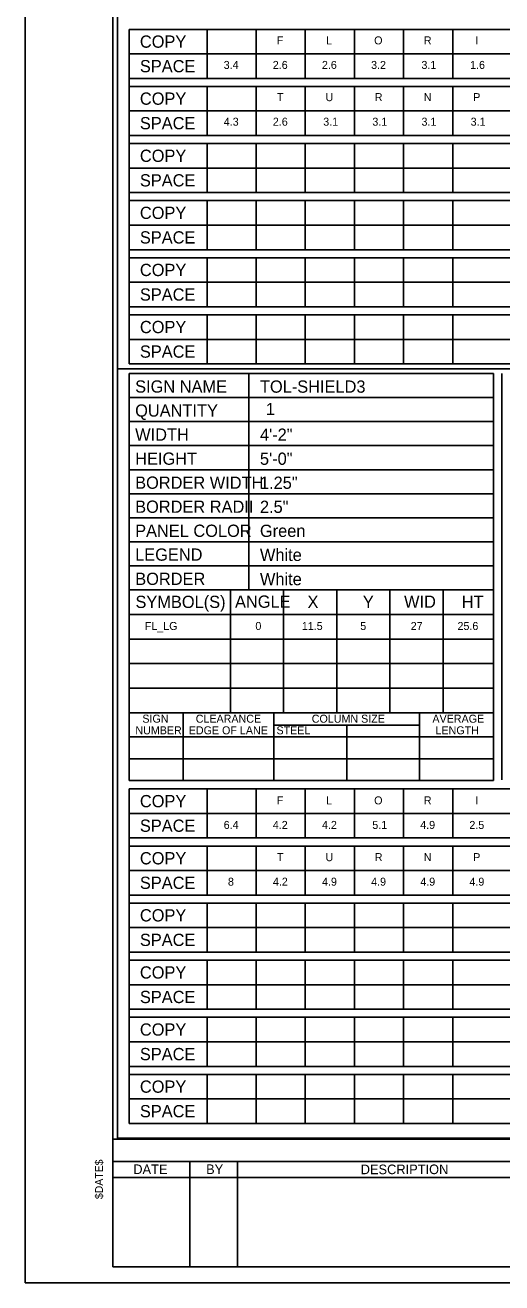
# Model space of a CAD drawing. Extents: x 17890628 to 17890844, y 17897693 to 17898031.
# Drawn here: x 17890700.5 to 17890726.4, y 17897907.6 to 17897976.1 of the extents above; entities that cross this region are included whole.
import ezdxf

# ---------------------------------------------------------------- set-up
doc = ezdxf.new("R2010")
doc.units = 0
for name, color, linetype in [('GSSign', 7, 'Continuous'), ('PlotBorder_dp', 7, 'Continuous'), ('SheetBorder_dp', 7, 'Continuous'), ('SheetLines_dp', 7, 'Continuous'), ('SheetLinesMisc2_dp', 7, 'Continuous'), ('TextMinor', 7, 'Continuous'), ('TextMisc', 7, 'Continuous')]:
    doc.layers.add(name, color=color, linetype=linetype)

msp = doc.modelspace()

# ---------------------------------------------------------------- linework, layer by layer
at = {"layer": 'PlotBorder_dp'}
msp.add_lwpolyline([(17890700.471, 17897907.61), (17890843.989, 17897907.61), (17890843.989, 17897999.809), (17890700.471, 17897999.809)], close=True, dxfattribs=at)
at = {"layer": 'SheetBorder_dp'}
for p, q in [((17890705.254, 17897998.94), (17890705.254, 17897908.479)), ((17890705.254, 17897915.438), (17890839.205, 17897915.438)), ((17890705.254, 17897908.479), (17890839.205, 17897908.479))]:
    msp.add_line(p, q, dxfattribs=at)
at = {"layer": 'SheetLines_dp'}
for p, q in [((17890705.254, 17897914.22), (17890755.355, 17897914.22)), ((17890709.43, 17897914.22), (17890709.43, 17897908.479)), ((17890712.039, 17897914.22), (17890712.039, 17897908.479)), ((17890705.254, 17897913.35), (17890755.355, 17897913.35))]:
    msp.add_line(p, q, dxfattribs=at)
at = {"layer": 'SheetLinesMisc2_dp'}
for p, q in [((17890705.5, 17897998.732), (17890705.5, 17897915.484)), ((17890706.142, 17897975.843), (17890771.912, 17897975.843)), ((17890706.142, 17897957.633), (17890706.142, 17897975.843)), ((17890710.375, 17897975.843), (17890710.375, 17897973.171)), ((17890713.051, 17897975.843), (17890713.051, 17897973.171)), ((17890715.727, 17897975.843), (17890715.727, 17897973.171)), ((17890718.402, 17897975.843), (17890718.402, 17897973.171)), ((17890721.077, 17897975.843), (17890721.077, 17897973.171)), ((17890723.753, 17897975.843), (17890723.753, 17897973.171)), ((17890706.142, 17897974.507), (17890771.912, 17897974.507)), ((17890706.142, 17897973.171), (17890771.912, 17897973.171)), ((17890706.142, 17897972.735), (17890771.912, 17897972.735)), ((17890710.375, 17897972.735), (17890710.375, 17897970.064)), ((17890713.051, 17897972.735), (17890713.051, 17897970.064)), ((17890715.727, 17897972.735), (17890715.727, 17897970.064)), ((17890718.402, 17897972.735), (17890718.402, 17897970.064)), ((17890721.077, 17897972.735), (17890721.077, 17897970.064)), ((17890723.753, 17897972.735), (17890723.753, 17897970.064)), ((17890706.142, 17897971.399), (17890771.912, 17897971.4)), ((17890706.142, 17897970.064), (17890771.912, 17897970.064)), ((17890706.142, 17897969.628), (17890771.912, 17897969.628)), ((17890710.375, 17897969.628), (17890710.375, 17897966.956)), ((17890713.051, 17897969.628), (17890713.051, 17897966.956)), ((17890715.727, 17897969.628), (17890715.727, 17897966.956)), ((17890718.402, 17897969.628), (17890718.402, 17897966.956)), ((17890721.077, 17897969.628), (17890721.077, 17897966.956)), ((17890723.753, 17897969.628), (17890723.753, 17897966.956)), ((17890706.142, 17897968.292), (17890771.912, 17897968.292)), ((17890706.142, 17897966.956), (17890771.912, 17897966.956)), ((17890706.142, 17897966.52), (17890771.912, 17897966.52)), ((17890710.375, 17897966.52), (17890710.375, 17897963.848)), ((17890713.051, 17897966.52), (17890713.051, 17897963.848)), ((17890715.727, 17897966.52), (17890715.727, 17897963.848)), ((17890718.402, 17897966.52), (17890718.402, 17897963.848)), ((17890721.077, 17897966.52), (17890721.077, 17897963.848)), ((17890723.753, 17897966.52), (17890723.753, 17897963.848)), ((17890706.142, 17897965.184), (17890771.912, 17897965.184)), ((17890706.142, 17897963.848), (17890771.912, 17897963.848)), ((17890706.142, 17897963.412), (17890771.912, 17897963.412)), ((17890710.375, 17897963.412), (17890710.375, 17897960.74)), ((17890713.051, 17897963.412), (17890713.051, 17897960.74)), ((17890715.727, 17897963.412), (17890715.727, 17897960.74)), ((17890718.402, 17897963.412), (17890718.402, 17897960.74)), ((17890721.077, 17897963.412), (17890721.077, 17897960.74)), ((17890723.753, 17897963.412), (17890723.753, 17897960.74)), ((17890706.142, 17897962.076), (17890771.912, 17897962.076)), ((17890706.142, 17897960.74), (17890771.912, 17897960.74)), ((17890706.142, 17897960.304), (17890771.912, 17897960.304)), ((17890710.375, 17897960.304), (17890710.375, 17897957.633)), ((17890713.051, 17897960.304), (17890713.051, 17897957.633)), ((17890715.727, 17897960.304), (17890715.727, 17897957.633)), ((17890718.402, 17897960.304), (17890718.402, 17897957.633)), ((17890721.077, 17897960.304), (17890721.077, 17897957.633)), ((17890723.753, 17897960.304), (17890723.753, 17897957.633)), ((17890706.142, 17897958.969), (17890771.912, 17897958.969)), ((17890705.5, 17897957.37), (17890839.233, 17897957.37)), ((17890706.142, 17897957.633), (17890771.912, 17897957.633)), ((17890706.142, 17897934.953), (17890706.142, 17897957.108)), ((17890706.142, 17897957.108), (17890725.973, 17897957.108)), ((17890712.643, 17897957.108), (17890712.643, 17897955.799)), ((17890725.973, 17897957.108), (17890725.973, 17897934.953)), ((17890726.429, 17897957.109), (17890726.429, 17897934.985)), ((17890706.142, 17897955.799), (17890725.973, 17897955.799)), ((17890712.643, 17897955.799), (17890712.643, 17897945.327)), ((17890706.142, 17897954.491), (17890725.973, 17897954.491)), ((17890706.142, 17897953.182), (17890725.973, 17897953.182)), ((17890706.142, 17897951.874), (17890725.973, 17897951.874)), ((17890706.142, 17897950.565), (17890725.973, 17897950.565)), ((17890706.142, 17897949.256), (17890725.973, 17897949.256)), ((17890706.142, 17897947.948), (17890716.057, 17897947.948)), ((17890716.057, 17897947.948), (17890725.973, 17897947.948)), ((17890706.142, 17897946.639), (17890716.057, 17897946.639)), ((17890716.057, 17897946.639), (17890725.973, 17897946.639)), ((17890706.141, 17897945.327), (17890725.973, 17897945.327)), ((17890711.644, 17897945.327), (17890711.644, 17897938.646)), ((17890714.542, 17897945.327), (17890714.542, 17897938.646)), ((17890717.44, 17897945.327), (17890717.44, 17897938.646)), ((17890720.337, 17897945.327), (17890720.337, 17897938.646)), ((17890723.235, 17897945.327), (17890723.235, 17897938.646)), ((17890706.141, 17897943.991), (17890725.973, 17897943.991)), ((17890706.141, 17897942.655), (17890725.973, 17897942.655)), ((17890706.141, 17897941.319), (17890725.973, 17897941.319)), ((17890706.141, 17897939.982), (17890725.973, 17897939.982)), ((17890706.141, 17897938.646), (17890725.973, 17897938.646)), ((17890709.08, 17897938.646), (17890709.08, 17897934.953)), ((17890714.015, 17897938.646), (17890714.015, 17897934.953)), ((17890721.947, 17897938.646), (17890721.947, 17897934.953)), ((17890714.015, 17897937.966), (17890721.947, 17897937.966)), ((17890717.981, 17897937.966), (17890717.981, 17897934.953)), ((17890706.141, 17897937.327), (17890725.973, 17897937.327)), ((17890706.141, 17897936.14), (17890725.973, 17897936.14)), ((17890706.142, 17897934.953), (17890725.973, 17897934.953)), ((17890706.142, 17897934.497), (17890771.912, 17897934.497)), ((17890706.142, 17897916.286), (17890706.142, 17897934.497)), ((17890710.375, 17897934.497), (17890710.375, 17897931.825)), ((17890713.051, 17897934.497), (17890713.051, 17897931.825)), ((17890715.727, 17897934.497), (17890715.727, 17897931.825)), ((17890718.402, 17897934.497), (17890718.402, 17897931.825)), ((17890721.077, 17897934.497), (17890721.077, 17897931.825)), ((17890723.753, 17897934.497), (17890723.753, 17897931.825)), ((17890706.142, 17897933.162), (17890771.912, 17897933.162)), ((17890706.142, 17897931.825), (17890771.912, 17897931.825)), ((17890706.142, 17897931.389), (17890771.912, 17897931.389)), ((17890710.375, 17897931.389), (17890710.375, 17897928.717)), ((17890713.051, 17897931.389), (17890713.051, 17897928.717)), ((17890715.727, 17897931.389), (17890715.727, 17897928.717)), ((17890718.402, 17897931.389), (17890718.402, 17897928.717)), ((17890721.077, 17897931.389), (17890721.077, 17897928.717)), ((17890723.753, 17897931.389), (17890723.753, 17897928.717)), ((17890706.142, 17897930.053), (17890771.912, 17897930.053)), ((17890706.142, 17897928.717), (17890771.912, 17897928.717)), ((17890706.142, 17897928.281), (17890771.912, 17897928.281)), ((17890710.375, 17897928.281), (17890710.375, 17897925.609)), ((17890713.051, 17897928.281), (17890713.051, 17897925.609)), ((17890715.727, 17897928.281), (17890715.727, 17897925.609)), ((17890718.402, 17897928.281), (17890718.402, 17897925.609)), ((17890721.077, 17897928.281), (17890721.077, 17897925.609)), ((17890723.753, 17897928.281), (17890723.753, 17897925.609)), ((17890706.142, 17897926.945), (17890771.912, 17897926.945)), ((17890706.142, 17897925.609), (17890771.912, 17897925.609)), ((17890706.142, 17897925.173), (17890771.912, 17897925.173)), ((17890710.375, 17897925.173), (17890710.375, 17897922.501)), ((17890713.051, 17897925.173), (17890713.051, 17897922.501)), ((17890715.727, 17897925.173), (17890715.727, 17897922.501)), ((17890718.402, 17897925.173), (17890718.402, 17897922.501)), ((17890721.077, 17897925.173), (17890721.077, 17897922.501)), ((17890723.753, 17897925.173), (17890723.753, 17897922.501)), ((17890706.142, 17897923.838), (17890771.912, 17897923.838)), ((17890706.142, 17897922.501), (17890771.912, 17897922.501)), ((17890706.142, 17897922.065), (17890771.912, 17897922.065)), ((17890710.375, 17897922.065), (17890710.375, 17897919.393)), ((17890713.051, 17897922.065), (17890713.051, 17897919.393)), ((17890715.727, 17897922.065), (17890715.727, 17897919.393)), ((17890718.402, 17897922.065), (17890718.402, 17897919.393)), ((17890721.077, 17897922.065), (17890721.077, 17897919.393)), ((17890723.753, 17897922.065), (17890723.753, 17897919.393)), ((17890706.142, 17897920.729), (17890771.912, 17897920.729)), ((17890706.142, 17897919.393), (17890771.912, 17897919.393)), ((17890706.142, 17897918.958), (17890771.912, 17897918.958)), ((17890710.375, 17897918.958), (17890710.375, 17897916.286)), ((17890713.051, 17897918.958), (17890713.051, 17897916.286)), ((17890715.727, 17897918.958), (17890715.727, 17897916.286)), ((17890718.402, 17897918.958), (17890718.402, 17897916.286)), ((17890721.077, 17897918.958), (17890721.077, 17897916.286)), ((17890723.753, 17897918.958), (17890723.753, 17897916.286)), ((17890706.142, 17897917.622), (17890771.912, 17897917.622)), ((17890706.142, 17897916.286), (17890771.912, 17897916.286)), ((17890705.5, 17897915.484), (17890839.233, 17897915.484))]:
    msp.add_line(p, q, dxfattribs=at)

# ---------------------------------------------------------------- texts
at = {"layer": 'GSSign'}
for s, height, p in [('F', 0.436, (17890714.174, 17897975.024)), ('L', 0.436, (17890716.855, 17897975.024)), ('O', 0.436, (17890719.475, 17897975.024)), ('R', 0.436, (17890722.181, 17897975.024)), ('I', 0.436, (17890724.984, 17897975.024)), ('3.4', 0.4357, (17890711.281, 17897973.688)), ('2.6', 0.4357, (17890713.956, 17897973.688)), ('2.6', 0.4357, (17890716.631, 17897973.688)), ('3.2', 0.4357, (17890719.309, 17897973.688)), ('3.1', 0.4357, (17890722.05, 17897973.688)), ('1.6', 0.4357, (17890724.699, 17897973.688)), ('T', 0.436, (17890714.181, 17897971.935)), ('U', 0.436, (17890716.828, 17897971.935)), ('R', 0.436, (17890719.51, 17897971.935)), ('N', 0.436, (17890722.178, 17897971.935)), ('P', 0.436, (17890724.87, 17897971.935)), ('4.3', 0.4357, (17890711.287, 17897970.598)), ('2.6', 0.4357, (17890713.96, 17897970.598)), ('3.1', 0.4357, (17890716.703, 17897970.598)), ('3.1', 0.4357, (17890719.378, 17897970.598)), ('3.1', 0.4357, (17890722.054, 17897970.598)), ('3.1', 0.4357, (17890724.729, 17897970.598)), ('TOL-SHIELD3', 0.66667, (17890713.256, 17897956.064)), ('1', 0.667, (17890713.581, 17897954.843)), ('4\'-2"', 0.6667, (17890713.256, 17897953.447)), ('5\'-0"', 0.6667, (17890713.256, 17897952.138)), ('1.25"', 0.6667, (17890713.256, 17897950.83)), ('2.5"', 0.6667, (17890713.256, 17897949.521)), ('Green', 0.6667, (17890713.256, 17897948.212)), ('White', 0.6667, (17890713.256, 17897946.904)), ('White', 0.6667, (17890713.256, 17897945.585)), ('FL_LG', 0.4357, (17890706.987, 17897943.147)), ('0', 0.436, (17890713.008, 17897943.147)), ('11.5', 0.4357, (17890715.538, 17897943.147)), ('5', 0.436, (17890718.717, 17897943.147)), ('27', 0.4357, (17890721.466, 17897943.147)), ('25.6', 0.4357, (17890724.013, 17897943.147)), ('F', 0.436, (17890714.174, 17897933.654)), ('L', 0.436, (17890716.855, 17897933.654)), ('O', 0.436, (17890719.475, 17897933.654)), ('R', 0.436, (17890722.181, 17897933.654)), ('I', 0.436, (17890724.984, 17897933.654)), ('6.4', 0.4357, (17890711.281, 17897932.318)), ('4.2', 0.4357, (17890713.958, 17897932.318)), ('4.2', 0.4357, (17890716.634, 17897932.318)), ('5.1', 0.4357, (17890719.375, 17897932.318)), ('4.9', 0.4357, (17890721.984, 17897932.318)), ('2.5', 0.4357, (17890724.66, 17897932.318)), ('T', 0.436, (17890714.181, 17897930.564)), ('U', 0.436, (17890716.828, 17897930.564)), ('R', 0.436, (17890719.51, 17897930.564)), ('N', 0.436, (17890722.178, 17897930.564)), ('P', 0.436, (17890724.87, 17897930.564)), ('8', 0.436, (17890711.514, 17897929.228)), ('4.2', 0.4357, (17890713.962, 17897929.228)), ('4.9', 0.4357, (17890716.637, 17897929.228)), ('4.9', 0.4357, (17890719.312, 17897929.228)), ('4.9', 0.4357, (17890721.987, 17897929.228)), ('4.9', 0.4357, (17890724.663, 17897929.228))]:
    msp.add_text(s, height=height, dxfattribs=at).set_placement(p)
at = {"layer": 'TextMinor'}
for s, height, p in [('COPY', 0.6667, (17890706.719, 17897974.843)), ('SPACE', 0.6667, (17890706.719, 17897973.507)), ('COPY', 0.6667, (17890706.719, 17897971.739)), ('SPACE', 0.6667, (17890706.719, 17897970.403)), ('COPY', 0.6667, (17890706.719, 17897968.628)), ('SPACE', 0.6667, (17890706.719, 17897967.292)), ('COPY', 0.6667, (17890706.719, 17897965.521)), ('SPACE', 0.6667, (17890706.719, 17897964.185)), ('COPY', 0.6667, (17890706.719, 17897962.413)), ('SPACE', 0.6667, (17890706.719, 17897961.076)), ('COPY', 0.6667, (17890706.719, 17897959.306)), ('SPACE', 0.6667, (17890706.719, 17897957.97)), ('SIGN NAME', 0.6667, (17890706.461, 17897956.068)), ('QUANTITY', 0.6667, (17890706.461, 17897954.76)), ('WIDTH', 0.6667, (17890706.461, 17897953.451)), ('HEIGHT', 0.6667, (17890706.461, 17897952.142)), ('BORDER WIDTH', 0.66667, (17890706.461, 17897950.834)), ('BORDER RADII', 0.66667, (17890706.461, 17897949.525)), ('PANEL COLOR', 0.66667, (17890706.461, 17897948.216)), ('LEGEND', 0.6667, (17890706.461, 17897946.919)), ('BORDER', 0.6667, (17890706.467, 17897945.599)), ('SYMBOL(S)', 0.6667, (17890706.478, 17897944.345)), ('ANGLE', 0.6667, (17890711.899, 17897944.358)), ('X', 0.667, (17890715.846, 17897944.345)), ('Y', 0.667, (17890718.859, 17897944.345)), ('WID', 0.6667, (17890721.103, 17897944.358)), ('HT', 0.6667, (17890724.244, 17897944.346)), ('SIGN', 0.4357, (17890706.852, 17897938.102)), ('CLEARANCE', 0.4357, (17890709.759, 17897938.1)), ('COLUMN SIZE', 0.43573, (17890716.077, 17897938.1)), ('AVERAGE', 0.4357, (17890722.648, 17897938.1)), ('NUMBER', 0.4357, (17890706.473, 17897937.468)), ('EDGE OF LANE', 0.43573, (17890709.38, 17897937.468)), ('STEEL    ', 0.4357, (17890714.156, 17897937.468)), ('LENGTH', 0.4357, (17890722.817, 17897937.468)), ('COPY', 0.6667, (17890706.719, 17897933.498)), ('SPACE', 0.6667, (17890706.719, 17897932.162)), ('COPY', 0.6667, (17890706.719, 17897930.389)), ('SPACE', 0.6667, (17890706.719, 17897929.053)), ('COPY', 0.6667, (17890706.719, 17897927.282)), ('SPACE', 0.6667, (17890706.719, 17897925.946)), ('COPY', 0.6667, (17890706.719, 17897924.173)), ('SPACE', 0.6667, (17890706.719, 17897922.838)), ('COPY', 0.6667, (17890706.719, 17897921.065)), ('SPACE', 0.6667, (17890706.719, 17897919.729)), ('COPY', 0.6667, (17890706.719, 17897917.958)), ('SPACE', 0.6667, (17890706.719, 17897916.622))]:
    msp.add_text(s, height=height, dxfattribs=at).set_placement(p)
msp.add_text('$DATE$', height=0.4262, rotation=90, dxfattribs=at).set_placement((17890704.706, 17897912.169))
at = {"layer": 'TextMisc'}
for s, height, rotation, p in [('DATE', 0.5219, 359.86925, (17890706.359, 17897913.533)), ('DESCRIPTION', 0.52178, 0.04975, (17890718.745, 17897913.524))]:
    msp.add_text(s, height=height, rotation=rotation, dxfattribs=at).set_placement(p)
msp.add_text('BY', height=0.5219, dxfattribs=at).set_placement((17890710.325, 17897913.533))

doc.saveas('drawing.dxf')
